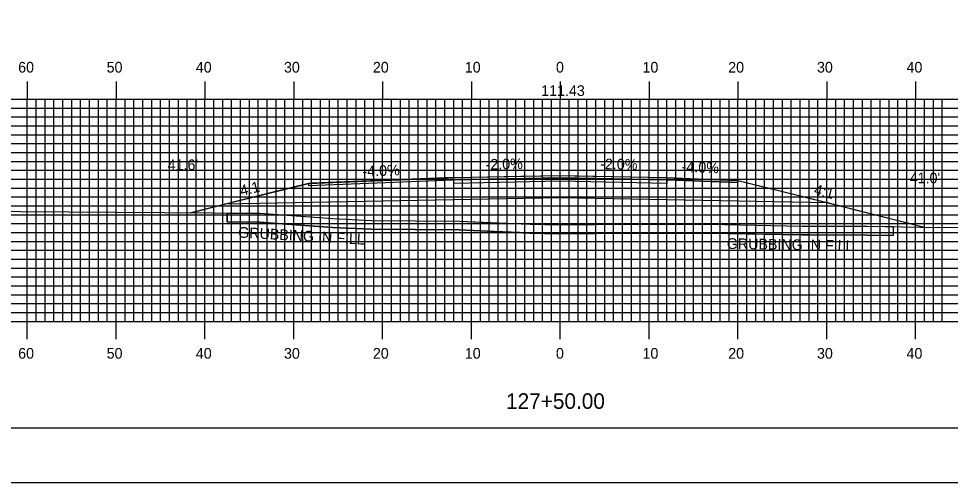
# Model space of a CAD drawing. Extents: x 1773596 to 1773940, y 442591 to 442811.
# Drawn here: x 1773701.2 to 1773806.1, y 442590.5 to 442642.7 of the extents above; entities that cross this region are included whole.
import ezdxf

# ---------------------------------------------------------------- set-up
doc = ezdxf.new("R2010")
doc.units = 0
for name, color, linetype in [('ANNOTATION', 7, 'Continuous'), ('BORDER', 7, 'Continuous'), ('D_Drainage_Culvert', 7, 'Continuous'), ('D_Roadway_Centerline', 7, 'Continuous'), ('D_Roadway_Centerline_Text', 7, 'Continuous'), ('D_Roadway_Edge_Shoulder', 7, 'Continuous'), ('D_Roadway_Edge_TW', 7, 'Continuous'), ('D_Roadway_Pavement', 7, 'Continuous'), ('D_Roadway_SubGrade', 7, 'Continuous'), ('D_Text_Standard', 7, 'Continuous'), ('GRUBBING IN FILL', 7, 'Continuous'), ('H_V ANNOTATION', 7, 'Continuous'), ('MAJOR', 7, 'Continuous'), ('MINOR', 7, 'Continuous'), ('PLOT BOUNDARY', 7, 'Continuous'), ('S_Roadway_Centerline', 7, 'Continuous')]:
    doc.layers.add(name, color=color, linetype=linetype)

msp = doc.modelspace()

# ---------------------------------------------------------------- linework, layer by layer
at = {"layer": 'BORDER'}
msp.add_lwpolyline([(1773612.55, 442596.67), (1773932.55, 442596.67), (1773932.55, 442806.67), (1773612.55, 442806.67)], close=True, dxfattribs=at)
at = {"layer": 'D_Drainage_Culvert'}
for p, q in [((1773750.15, 442624.85), (1773734.15, 442624.21)), ((1773774.15, 442624.85), (1773782.15, 442624.53))]:
    msp.add_line(p, q, dxfattribs=at)
for points in [[(1773782.15, 442624.53), (1773786.15, 442623.53), (1773803.16, 442619.28)], [(1773733.81, 442624.2), (1773729.81, 442623.2), (1773720.57, 442620.89)]]:
    msp.add_lwpolyline(points, dxfattribs=at)
at = {"layer": 'D_Roadway_Centerline'}
msp.add_lwpolyline([(1773720.57, 442620.89), (1773724.36, 442621.84), (1773733.81, 442624.2), (1773748.68, 442624.8), (1773750.15, 442624.85), (1773757.71, 442625.01), (1773762.15, 442625.09), (1773763.75, 442625.06), (1773774.14, 442624.85), (1773774.15, 442624.85), (1773778.3, 442624.69), (1773782.15, 442624.53), (1773792.32, 442621.99), (1773803.16, 442619.28)], dxfattribs=at)
at = {"layer": 'D_Roadway_Edge_Shoulder'}
for points in [[(1773750.15, 442624.85), (1773733.81, 442624.2), (1773733.81, 442623.95), (1773750.15, 442624.6)], [(1773774.15, 442624.85), (1773782.15, 442624.53), (1773782.15, 442624.28), (1773774.15, 442624.6)]]:
    msp.add_lwpolyline(points, close=True, dxfattribs=at)
at = {"layer": 'D_Roadway_Edge_TW'}
msp.add_lwpolyline([(1773750.15, 442624.6), (1773750.15, 442624.85), (1773762.15, 442625.09), (1773774.15, 442624.85), (1773774.15, 442624.6), (1773762.15, 442624.84)], close=True, dxfattribs=at)
at = {"layer": 'D_Roadway_Pavement'}
msp.add_lwpolyline([(1773750.15, 442624.19), (1773750.15, 442624.6), (1773762.15, 442624.84), (1773774.15, 442624.6), (1773774.15, 442624.19), (1773762.15, 442624.43)], close=True, dxfattribs=at)
at = {"layer": 'D_Roadway_SubGrade'}
msp.add_lwpolyline([(1773750.15, 442622.35), (1773724.36, 442621.84), (1773733.81, 442624.2), (1773733.81, 442623.95), (1773750.15, 442624.6), (1773762.15, 442624.84), (1773774.15, 442624.6), (1773782.15, 442624.28), (1773782.15, 442624.53), (1773792.32, 442621.99), (1773774.15, 442622.35), (1773762.15, 442622.59)], close=True, dxfattribs=at)
at = {"layer": 'GRUBBING IN FILL'}
for p, q in [((1773724.66, 442620.86), (1773724.66, 442619.86)), ((1773724.66, 442620.86), (1773724.66, 442619.86)), ((1773799.63, 442619.33), (1773799.63, 442618.33)), ((1773799.63, 442619.33), (1773799.63, 442618.33))]:
    msp.add_line(p, q, dxfattribs=at)
for points in [[(1773724.66, 442620.86), (1773728.32, 442620.83), (1773732.43, 442620.54), (1773736.55, 442620.25), (1773740.9, 442620.02), (1773745.85, 442619.99), (1773750.8, 442619.96), (1773754.78, 442619.77), (1773758.76, 442619.59), (1773762.15, 442619.52), (1773762.15, 442618.52), (1773760.38, 442618.56), (1773754.75, 442618.77), (1773750.77, 442618.96), (1773745.82, 442618.99), (1773740.87, 442619.03), (1773736.49, 442619.25), (1773732.38, 442619.54), (1773728.28, 442619.83), (1773724.66, 442619.86)], [(1773724.66, 442620.86), (1773728.32, 442620.83), (1773732.43, 442620.54), (1773736.55, 442620.25), (1773740.9, 442620.02), (1773745.85, 442619.99), (1773750.8, 442619.96), (1773754.78, 442619.77), (1773758.76, 442619.59), (1773762.15, 442619.52), (1773762.15, 442618.52), (1773760.38, 442618.56), (1773754.75, 442618.77), (1773750.77, 442618.96), (1773745.82, 442618.99), (1773740.87, 442619.03), (1773736.49, 442619.25), (1773732.38, 442619.54), (1773728.28, 442619.83), (1773724.66, 442619.86)], [(1773762.15, 442619.52), (1773765.97, 442619.57), (1773772.44, 442619.59), (1773778.91, 442619.6), (1773784.12, 442619.5), (1773789.34, 442619.39), (1773793.02, 442619.38), (1773796.7, 442619.37), (1773799.63, 442619.33), (1773799.63, 442618.33), (1773796.69, 442618.37), (1773793.01, 442618.38), (1773784.11, 442618.5), (1773778.9, 442618.6), (1773772.44, 442618.59), (1773765.98, 442618.57), (1773762.15, 442618.52)], [(1773762.15, 442619.52), (1773765.97, 442619.57), (1773772.44, 442619.59), (1773778.91, 442619.6), (1773784.12, 442619.5), (1773789.34, 442619.39), (1773793.02, 442619.38), (1773796.7, 442619.37), (1773799.63, 442619.33), (1773799.63, 442618.33), (1773796.69, 442618.37), (1773793.01, 442618.38), (1773784.11, 442618.5), (1773778.9, 442618.6), (1773772.44, 442618.59), (1773765.98, 442618.57), (1773762.15, 442618.52)]]:
    msp.add_lwpolyline(points, close=True, dxfattribs=at)
msp.add_lwpolyline([(1773724.66, 442619.86), (1773728.28, 442619.83), (1773736.49, 442619.25), (1773740.87, 442619.03), (1773750.77, 442618.96), (1773758.72, 442618.59), (1773762.03, 442618.52), (1773765.98, 442618.57), (1773778.9, 442618.6), (1773789.33, 442618.39), (1773796.69, 442618.37), (1773799.63, 442618.33)], dxfattribs=at)
msp.add_lwpolyline([(1773724.66, 442619.86), (1773728.28, 442619.83), (1773736.49, 442619.25), (1773740.87, 442619.03), (1773750.77, 442618.96), (1773758.72, 442618.59), (1773762.03, 442618.52), (1773765.98, 442618.57), (1773778.9, 442618.6), (1773789.33, 442618.39), (1773796.69, 442618.37), (1773799.63, 442618.33)], dxfattribs=at)
at = {"layer": 'MAJOR'}
for p, q in [((1773702.15, 442635.67), (1773702.15, 442633.67)), ((1773712.15, 442635.67), (1773712.15, 442633.67)), ((1773722.15, 442635.67), (1773722.15, 442633.67)), ((1773732.15, 442635.67), (1773732.15, 442633.67)), ((1773742.15, 442635.67), (1773742.15, 442633.67)), ((1773752.15, 442635.67), (1773752.15, 442633.67)), ((1773762.15, 442635.67), (1773762.15, 442633.67)), ((1773772.15, 442635.67), (1773772.15, 442633.67)), ((1773782.15, 442635.67), (1773782.15, 442633.67)), ((1773792.15, 442635.67), (1773792.15, 442633.67)), ((1773802.15, 442635.67), (1773802.15, 442633.67)), ((1773622.15, 442633.67), (1773902.15, 442633.67)), ((1773622.15, 442633.67), (1773902.15, 442633.67)), ((1773702.15, 442608.67), (1773702.15, 442633.67)), ((1773712.15, 442608.67), (1773712.15, 442633.67)), ((1773722.15, 442608.67), (1773722.15, 442633.67)), ((1773732.15, 442608.67), (1773732.15, 442633.67)), ((1773742.15, 442608.67), (1773742.15, 442633.67)), ((1773752.15, 442608.67), (1773752.15, 442633.67)), ((1773762.15, 442608.67), (1773762.15, 442633.67)), ((1773772.15, 442608.67), (1773772.15, 442633.67)), ((1773782.15, 442608.67), (1773782.15, 442633.67)), ((1773792.15, 442608.67), (1773792.15, 442633.67)), ((1773802.15, 442608.67), (1773802.15, 442633.67)), ((1773622.15, 442628.67), (1773902.15, 442628.67)), ((1773622.15, 442623.67), (1773902.15, 442623.67)), ((1773622.15, 442618.67), (1773902.15, 442618.67)), ((1773622.15, 442613.67), (1773902.15, 442613.67)), ((1773622.15, 442608.67), (1773902.15, 442608.67)), ((1773622.15, 442608.67), (1773902.15, 442608.67)), ((1773702.15, 442606.66), (1773702.15, 442608.67)), ((1773712.15, 442606.66), (1773712.15, 442608.67)), ((1773722.15, 442606.66), (1773722.15, 442608.67)), ((1773732.15, 442606.66), (1773732.15, 442608.67)), ((1773742.15, 442606.66), (1773742.15, 442608.67)), ((1773752.15, 442606.66), (1773752.15, 442608.67)), ((1773762.15, 442606.66), (1773762.15, 442608.67)), ((1773772.15, 442606.66), (1773772.15, 442608.67)), ((1773782.15, 442606.66), (1773782.15, 442608.67)), ((1773792.15, 442606.66), (1773792.15, 442608.67)), ((1773802.15, 442606.66), (1773802.15, 442608.67))]:
    msp.add_line(p, q, dxfattribs=at)
at = {"layer": 'MINOR'}
for p, q in [((1773703.15, 442608.67), (1773703.15, 442633.67)), ((1773704.15, 442608.67), (1773704.15, 442633.67)), ((1773705.15, 442608.67), (1773705.15, 442633.67)), ((1773706.15, 442608.67), (1773706.15, 442633.67)), ((1773707.15, 442608.67), (1773707.15, 442633.67)), ((1773708.15, 442608.67), (1773708.15, 442633.67)), ((1773709.15, 442608.67), (1773709.15, 442633.67)), ((1773710.15, 442608.67), (1773710.15, 442633.67)), ((1773711.15, 442608.67), (1773711.15, 442633.67)), ((1773713.15, 442608.67), (1773713.15, 442633.67)), ((1773714.15, 442608.67), (1773714.15, 442633.67)), ((1773715.15, 442608.67), (1773715.15, 442633.67)), ((1773716.15, 442608.67), (1773716.15, 442633.67)), ((1773717.15, 442608.67), (1773717.15, 442633.67)), ((1773718.15, 442608.67), (1773718.15, 442633.67)), ((1773719.15, 442608.67), (1773719.15, 442633.67)), ((1773720.15, 442608.67), (1773720.15, 442633.67)), ((1773721.15, 442608.67), (1773721.15, 442633.67)), ((1773723.15, 442608.67), (1773723.15, 442633.67)), ((1773724.15, 442608.67), (1773724.15, 442633.67)), ((1773725.15, 442608.67), (1773725.15, 442633.67)), ((1773726.15, 442608.67), (1773726.15, 442633.67)), ((1773727.15, 442608.67), (1773727.15, 442633.67)), ((1773728.15, 442608.67), (1773728.15, 442633.67)), ((1773729.15, 442608.67), (1773729.15, 442633.67)), ((1773730.15, 442608.67), (1773730.15, 442633.67)), ((1773731.15, 442608.67), (1773731.15, 442633.67)), ((1773733.15, 442608.67), (1773733.15, 442633.67)), ((1773734.15, 442608.67), (1773734.15, 442633.67)), ((1773735.15, 442608.67), (1773735.15, 442633.67)), ((1773736.15, 442608.67), (1773736.15, 442633.67)), ((1773737.15, 442608.67), (1773737.15, 442633.67)), ((1773738.15, 442608.67), (1773738.15, 442633.67)), ((1773739.15, 442608.67), (1773739.15, 442633.67)), ((1773740.15, 442608.67), (1773740.15, 442633.67)), ((1773741.15, 442608.67), (1773741.15, 442633.67)), ((1773743.15, 442608.67), (1773743.15, 442633.67)), ((1773744.15, 442608.67), (1773744.15, 442633.67)), ((1773745.15, 442608.67), (1773745.15, 442633.67)), ((1773746.15, 442608.67), (1773746.15, 442633.67)), ((1773747.15, 442608.67), (1773747.15, 442633.67)), ((1773748.15, 442608.67), (1773748.15, 442633.67)), ((1773749.15, 442608.67), (1773749.15, 442633.67)), ((1773750.15, 442608.67), (1773750.15, 442633.67)), ((1773751.15, 442608.67), (1773751.15, 442633.67)), ((1773753.15, 442608.67), (1773753.15, 442633.67)), ((1773754.15, 442608.67), (1773754.15, 442633.67)), ((1773755.15, 442608.67), (1773755.15, 442633.67)), ((1773756.15, 442608.67), (1773756.15, 442633.67)), ((1773757.15, 442608.67), (1773757.15, 442633.67)), ((1773758.15, 442608.67), (1773758.15, 442633.67)), ((1773759.15, 442608.67), (1773759.15, 442633.67)), ((1773760.15, 442608.67), (1773760.15, 442633.67)), ((1773761.15, 442608.67), (1773761.15, 442633.67)), ((1773763.15, 442608.67), (1773763.15, 442633.67)), ((1773764.15, 442608.67), (1773764.15, 442633.67)), ((1773765.15, 442608.67), (1773765.15, 442633.67)), ((1773766.15, 442608.67), (1773766.15, 442633.67)), ((1773767.15, 442608.67), (1773767.15, 442633.67)), ((1773768.15, 442608.67), (1773768.15, 442633.67)), ((1773769.15, 442608.67), (1773769.15, 442633.67)), ((1773770.15, 442608.67), (1773770.15, 442633.67)), ((1773771.15, 442608.67), (1773771.15, 442633.67)), ((1773773.15, 442608.67), (1773773.15, 442633.67)), ((1773774.15, 442608.67), (1773774.15, 442633.67)), ((1773775.15, 442608.67), (1773775.15, 442633.67)), ((1773776.15, 442608.67), (1773776.15, 442633.67)), ((1773777.15, 442608.67), (1773777.15, 442633.67)), ((1773778.15, 442608.67), (1773778.15, 442633.67)), ((1773779.15, 442608.67), (1773779.15, 442633.67)), ((1773780.15, 442608.67), (1773780.15, 442633.67)), ((1773781.15, 442608.67), (1773781.15, 442633.67)), ((1773783.15, 442608.67), (1773783.15, 442633.67)), ((1773784.15, 442608.67), (1773784.15, 442633.67)), ((1773785.15, 442608.67), (1773785.15, 442633.67)), ((1773786.15, 442608.67), (1773786.15, 442633.67)), ((1773787.15, 442608.67), (1773787.15, 442633.67)), ((1773788.15, 442608.67), (1773788.15, 442633.67)), ((1773789.15, 442608.67), (1773789.15, 442633.67)), ((1773790.15, 442608.67), (1773790.15, 442633.67)), ((1773791.15, 442608.67), (1773791.15, 442633.67)), ((1773793.15, 442608.67), (1773793.15, 442633.67)), ((1773794.15, 442608.67), (1773794.15, 442633.67)), ((1773795.15, 442608.67), (1773795.15, 442633.67)), ((1773796.15, 442608.67), (1773796.15, 442633.67)), ((1773797.15, 442608.67), (1773797.15, 442633.67)), ((1773798.15, 442608.67), (1773798.15, 442633.67)), ((1773799.15, 442608.67), (1773799.15, 442633.67)), ((1773800.15, 442608.67), (1773800.15, 442633.67)), ((1773801.15, 442608.67), (1773801.15, 442633.67)), ((1773803.15, 442608.67), (1773803.15, 442633.67)), ((1773804.15, 442608.67), (1773804.15, 442633.67)), ((1773805.15, 442608.67), (1773805.15, 442633.67)), ((1773622.15, 442632.67), (1773902.15, 442632.67)), ((1773622.15, 442631.67), (1773902.15, 442631.67)), ((1773622.15, 442630.67), (1773902.15, 442630.67)), ((1773622.15, 442629.67), (1773902.15, 442629.67)), ((1773622.15, 442627.67), (1773902.15, 442627.67)), ((1773622.15, 442626.67), (1773902.15, 442626.67)), ((1773622.15, 442625.67), (1773902.15, 442625.67)), ((1773622.15, 442624.67), (1773902.15, 442624.67)), ((1773622.15, 442622.67), (1773902.15, 442622.67)), ((1773622.15, 442621.67), (1773902.15, 442621.67)), ((1773622.15, 442620.67), (1773902.15, 442620.67)), ((1773622.15, 442619.67), (1773902.15, 442619.67)), ((1773622.15, 442617.67), (1773902.15, 442617.67)), ((1773622.15, 442616.67), (1773902.15, 442616.67)), ((1773622.15, 442615.67), (1773902.15, 442615.67)), ((1773622.15, 442614.67), (1773902.15, 442614.67)), ((1773622.15, 442612.67), (1773902.15, 442612.67)), ((1773622.15, 442611.67), (1773902.15, 442611.67)), ((1773622.15, 442610.67), (1773902.15, 442610.67)), ((1773622.15, 442609.67), (1773902.15, 442609.67))]:
    msp.add_line(p, q, dxfattribs=at)
at = {"layer": 'PLOT BOUNDARY'}
msp.add_lwpolyline([(1773596.36, 442590.55), (1773936.36, 442590.55), (1773936.36, 442810.55), (1773596.36, 442810.55)], close=True, dxfattribs=at)
at = {"layer": 'S_Roadway_Centerline'}
msp.add_lwpolyline([(1773622.15, 442622.07), (1773628.78, 442622.1), (1773641.49, 442622.14), (1773646.29, 442622.02), (1773650.45, 442621.94), (1773665.38, 442621.7), (1773671.81, 442621.6), (1773681.15, 442621.27), (1773690.98, 442621.16), (1773692.57, 442621.1), (1773693.82, 442621.1), (1773696.01, 442621.08), (1773728.32, 442620.83), (1773736.55, 442620.25), (1773740.9, 442620.02), (1773750.8, 442619.96), (1773758.76, 442619.59), (1773762.04, 442619.52), (1773765.97, 442619.57), (1773778.91, 442619.6), (1773789.34, 442619.39), (1773796.7, 442619.37), (1773802.63, 442619.28), (1773812.5, 442619.22)], dxfattribs=at)

# ---------------------------------------------------------------- texts
at = {"layer": 'ANNOTATION'}
for s, rotation, p in [('-2.0%', 1.1458, (1773753.75, 442625.73)), ('-2.0%', 358.8543, (1773766.63, 442625.8)), ('-4.0%', 357.7093, (1773775.79, 442625.5)), ('-4.0%', 2.2907, (1773739.9, 442624.95)), ('4:1', 14.0392, (1773726.26, 442622.76)), ('4:1', 345.9658, (1773790.62, 442622.97))]:
    msp.add_text(s, height=1.2, rotation=rotation, dxfattribs=at).set_placement(p)
at = {"layer": 'D_Roadway_Centerline'}
for s, p in [('C', (1773762.14, 442625.09)), ('L', (1773762.15, 442625.09))]:
    msp.add_text(s, height=0.0146, dxfattribs=at).set_placement(p)
at = {"layer": 'D_Roadway_Centerline_Text'}
msp.add_text('111.43', height=1.2, dxfattribs=at).set_placement((1773760, 442634.04))
at = {"layer": 'D_Text_Standard'}
for s, p in [("41.6'", (1773717.95, 442625.69)), ("41.0'", (1773801.48, 442624.21))]:
    msp.add_text(s, height=1.2, dxfattribs=at).set_placement(p)
at = {"layer": 'GRUBBING IN FILL'}
for rotation, p in [(356.7272, (1773725.86, 442618.11)), (359.0192, (1773780.88, 442616.83))]:
    msp.add_text('GRUBBING IN FILL', height=1.2, rotation=rotation, dxfattribs=at).set_placement(p)
at = {"layer": 'H_V ANNOTATION'}
for s, height, p in [('60', 1.2, (1773701.12, 442636.67)), ('50', 1.2, (1773711.08, 442636.67)), ('40', 1.2, (1773721.12, 442636.67)), ('30', 1.2, (1773731.04, 442636.67)), ('20', 1.2, (1773741.05, 442636.67)), ('10', 1.2, (1773751.4, 442636.67)), ('0', 1.2, (1773761.66, 442636.67)), ('10', 1.2, (1773771.4, 442636.67)), ('20', 1.2, (1773781.05, 442636.67)), ('30', 1.2, (1773791.04, 442636.67)), ('40', 1.2, (1773801.12, 442636.67)), ('60', 1.2, (1773701.12, 442604.47)), ('50', 1.2, (1773711.08, 442604.47)), ('40', 1.2, (1773721.12, 442604.47)), ('30', 1.2, (1773731.04, 442604.47)), ('20', 1.2, (1773741.05, 442604.47)), ('10', 1.2, (1773751.4, 442604.47)), ('0', 1.2, (1773761.66, 442604.47)), ('10', 1.2, (1773771.4, 442604.47)), ('20', 1.2, (1773781.05, 442604.47)), ('30', 1.2, (1773791.04, 442604.47)), ('40', 1.2, (1773801.12, 442604.47)), ('127+50.00', 1.75, (1773756.04, 442598.82))]:
    msp.add_text(s, height=height, dxfattribs=at).set_placement(p)

doc.saveas('drawing.dxf')
